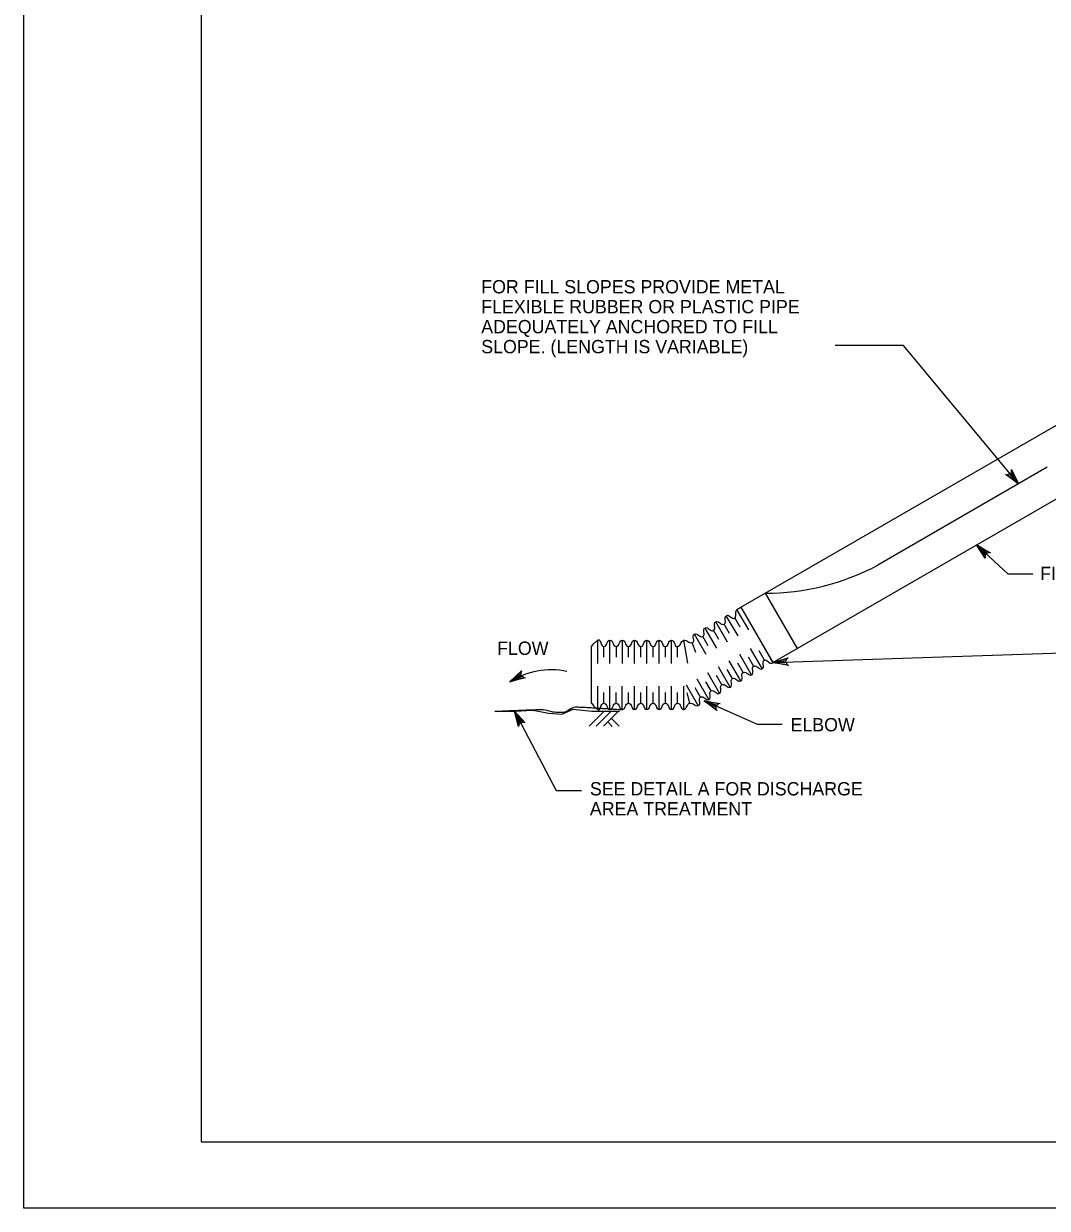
# Model space of a CAD drawing. Extents: x 636462 to 637367, y 299944 to 300538.
# Drawn here: x 636461.9 to 636692.5, y 299944.4 to 300211.3 of the extents above; entities that cross this region are included whole.
import ezdxf

# ---------------------------------------------------------------- set-up
doc = ezdxf.new("R2010")
doc.units = 0
for name, color, linetype in [('1', 7, 'Continuous'), ('Default', 7, 'Continuous'), ('PLT-BNDY', 7, 'Continuous')]:
    doc.layers.add(name, color=color, linetype=linetype)

# ---------------------------------------------------------------- blocks, each defined once
blk = doc.blocks.new('SC9446')
at = {"layer": 'Default'}
blk.add_line((0, 0), (0, 0), dxfattribs=at)

msp = doc.modelspace()

# ---------------------------------------------------------------- linework, layer by layer
at = {"layer": '1'}
msp.add_lwpolyline([(637287.91, 299959.45), (637287.91, 300523.45), (636501.91, 300523.45), (636501.91, 299959.45), (637287.91, 299959.45), (637287.91, 299985.81), (637087.91, 299985.81), (637087.91, 300050.49), (637287.91, 300050.49), (637287.91, 300079.45), (637087.91, 300079.45), (637087.91, 299959.45), (637166.72, 299959.45), (637166.72, 299985.81), (637166.72, 299959.45), (637243.72, 299959.45), (637243.72, 299985.81), (637243.72, 299973.49), (637287.91, 299973.49)], dxfattribs=at)
at = {"layer": 'Default'}
for p, q in [((636628.96, 300083.01), (636710.74, 300130.22)), ((636636.14, 300070.58), (636717.92, 300117.79)), ((636692.52, 300111.42), (636654.36, 300089.38)), ((636623.51, 300079.86), (636628.96, 300083.01)), ((636628.96, 300083.01), (636636.14, 300070.58)), ((636622.61, 300079.34), (636623.51, 300079.86)), ((636625.25, 300074.79), (636622.61, 300079.34)), ((636623.51, 300079.86), (636630.69, 300067.43)), ((636620.45, 300072.02), (636617.82, 300076.57)), ((636622.85, 300073.4), (636620.21, 300077.96)), ((636623.31, 300075.36), (636622.11, 300077.45)), ((636615.65, 300069.25), (636613.02, 300073.8)), ((636618.05, 300070.63), (636615.42, 300075.19)), ((636618.52, 300072.59), (636617.31, 300074.68)), ((636620.92, 300073.98), (636619.71, 300076.07)), ((636589.85, 300058.24), (636589.85, 300071.04)), ((636591.23, 300067.16), (636591.23, 300072.42)), ((636592.62, 300068.62), (636592.62, 300071.04)), ((636594, 300067.16), (636594, 300072.42)), ((636595.39, 300071.04), (636595.39, 300068.62)), ((636596.77, 300072.42), (636596.77, 300067.16)), ((636598.16, 300068.62), (636598.16, 300071.04)), ((636599.54, 300067.16), (636599.54, 300072.42)), ((636600.93, 300068.62), (636600.93, 300071.04)), ((636602.31, 300067.16), (636602.31, 300072.42)), ((636603.7, 300068.62), (636603.7, 300071.04)), ((636605.08, 300067.16), (636605.08, 300072.42)), ((636606.47, 300068.62), (636606.47, 300071.04)), ((636607.85, 300067.16), (636607.85, 300072.42)), ((636609.24, 300068.62), (636609.24, 300071.04)), ((636611.54, 300067.24), (636610.62, 300072.42)), ((636613.34, 300069.64), (636612.51, 300071.91)), ((636616.12, 300071.21), (636614.91, 300073.3)), ((636630.69, 300067.43), (636628.06, 300071.99)), ((636625.89, 300064.66), (636623.26, 300069.22)), ((636626.4, 300066.55), (636625.19, 300068.64)), ((636628.29, 300066.04), (636625.66, 300070.6)), ((636628.8, 300067.93), (636627.59, 300070.03)), ((636630.69, 300067.43), (636636.14, 300070.58)), ((636621.09, 300061.89), (636618.46, 300066.45)), ((636621.6, 300063.78), (636620.39, 300065.87)), ((636623.49, 300063.27), (636620.86, 300067.83)), ((636624, 300065.17), (636622.79, 300067.26)), ((636616.3, 300059.12), (636613.67, 300063.68)), ((636616.8, 300061.01), (636615.6, 300063.1)), ((636618.7, 300060.5), (636616.06, 300065.06)), ((636619.2, 300062.4), (636617.99, 300064.49)), ((636591.23, 300056.86), (636591.23, 300062.12)), ((636592.62, 300058.24), (636592.62, 300060.65)), ((636594, 300056.86), (636594, 300062.12)), ((636595.39, 300058.24), (636595.39, 300060.66)), ((636596.77, 300056.86), (636596.77, 300062.12)), ((636598.16, 300058.24), (636598.16, 300060.66)), ((636599.54, 300056.86), (636599.54, 300062.12)), ((636600.93, 300058.24), (636600.93, 300060.66)), ((636602.31, 300056.86), (636602.31, 300062.12)), ((636603.7, 300058.24), (636603.7, 300060.66)), ((636605.08, 300056.86), (636605.08, 300062.12)), ((636606.47, 300058.24), (636606.47, 300060.66)), ((636607.85, 300056.86), (636607.85, 300062.12)), ((636609.24, 300058.24), (636609.24, 300060.66)), ((636610.62, 300056.86), (636610.62, 300062.12)), ((636613.9, 300057.73), (636611.27, 300062.29)), ((636612.01, 300058.24), (636611.38, 300060.57)), ((636614.4, 300059.63), (636613.2, 300061.72)), ((636589.31, 300053.08), (636592.68, 300056.46)), ((636590.88, 300053.08), (636594.27, 300056.47)), ((636592.52, 300053.08), (636595.9, 300056.47)), ((636593.48, 300054.04), (636594.49, 300053.03)), ((636594.29, 300054.86), (636596.07, 300053.08))]:
    msp.add_line(p, q, dxfattribs=at)
for points in [[(636686.04, 300107.67), (636660.14, 300138.85), (636644.73, 300138.85)], [(636684.45, 300110.56), (636684.45, 300110.91), (636686.04, 300107.67), (636684.45, 300110.56), (636684.29, 300110.17), (636686.04, 300107.67), (636683.9, 300109.83), (636683.49, 300109.73), (636686.04, 300107.67), (636683.12, 300109.78), (636683.49, 300109.73)], [(636676.6, 300093.94), (636683.62, 300087.36), (636689.29, 300087.36)], [(636678.49, 300091.24), (636678.53, 300090.89), (636676.6, 300093.94), (636678.49, 300091.24), (636678.61, 300091.64), (636676.6, 300093.94), (636678.97, 300092.02), (636679.36, 300092.17), (636676.6, 300093.94), (636679.74, 300092.16), (636679.36, 300092.17)], [(636633.95, 300066.95), (636634.23, 300066.75), (636630.68, 300067.4), (636633.95, 300066.95), (636633.73, 300067.32), (636630.68, 300067.4), (636633.69, 300067.84), (636633.85, 300068.22), (636630.68, 300067.4), (636634.12, 300068.49), (636633.85, 300068.22)], [(636630.69, 300067.43), (636729.67, 300070.74), (636735.34, 300070.74)], [(636574.59, 300064.05), (636574.94, 300063.98), (636571.45, 300063.05), (636574.59, 300064.05), (636574.24, 300064.28), (636571.45, 300063.05), (636573.98, 300064.73), (636573.96, 300065.15), (636571.45, 300063.05), (636574.09, 300065.51), (636573.96, 300065.15)], [(636617.92, 300056.9), (636618.08, 300056.59), (636615.24, 300058.81), (636617.92, 300056.9), (636617.9, 300057.32), (636615.24, 300058.81), (636618.11, 300057.8), (636618.43, 300058.07), (636615.24, 300058.81), (636618.79, 300058.18), (636618.43, 300058.07)], [(636615.48, 300058.69), (636627.15, 300053.49), (636632.82, 300053.49)], [(636568.31, 300056.47), (636572.48, 300056.47), (636576.66, 300056.71), (636580.14, 300056.01), (636583.16, 300055.78), (636585.71, 300056.94), (636589.89, 300056.47), (636596.16, 300056.47)], [(636572.48, 300056.47), (636581.88, 300038.57), (636587.55, 300038.57)], [(636573.46, 300053.33), (636573.39, 300052.98), (636572.48, 300056.47), (636573.46, 300053.33), (636573.69, 300053.68), (636572.48, 300056.47), (636574.15, 300053.93), (636574.57, 300053.95), (636572.48, 300056.47), (636574.92, 300053.82), (636574.57, 300053.95)]]:
    msp.add_lwpolyline(points, dxfattribs=at)
for centre, radius, start, end in [((636629.06, 300136.39), 53.38, 269.892, 298.2877), ((636580.73, 300048.58), 17.19, 78.1581, 122.6576)]:
    msp.add_arc(centre, radius, start, end, dxfattribs=at)
for points in [[(636589.85, 300071.04), (636590.31, 300071.65), (636590.77, 300072.09), (636591.23, 300072.42), (636591.7, 300072.75), (636592.16, 300071.04), (636592.62, 300071.04), (636593.08, 300071.04), (636593.54, 300072.42), (636594, 300072.42), (636594.47, 300072.42), (636594.93, 300071.04), (636595.39, 300071.04), (636595.85, 300071.04), (636596.31, 300072.42), (636596.77, 300072.42), (636597.24, 300072.42), (636597.7, 300071.04), (636598.16, 300071.04), (636598.62, 300071.04), (636599.08, 300072.42), (636599.54, 300072.42), (636600, 300072.42), (636600.47, 300071.04), (636600.93, 300071.04), (636601.39, 300071.04), (636601.85, 300072.42), (636602.31, 300072.42), (636602.77, 300072.42), (636603.24, 300071.04), (636603.7, 300071.04), (636604.16, 300071.04), (636604.62, 300072.42), (636605.08, 300072.42), (636605.54, 300072.42), (636606, 300071.04), (636606.47, 300071.04), (636606.93, 300071.04), (636607.39, 300072.42), (636607.85, 300072.42), (636608.31, 300072.42), (636608.77, 300070.95), (636609.24, 300071.04), (636609.7, 300071.12), (636610.16, 300072.3), (636610.62, 300072.42), (636611.08, 300072.54), (636612.01, 300071.73), (636612.51, 300071.91), (636613.02, 300072.1), (636612.62, 300073.57), (636613.02, 300073.8), (636613.42, 300074.03), (636614.51, 300073.07), (636614.91, 300073.3), (636615.31, 300073.53), (636615.02, 300074.96), (636615.42, 300075.19), (636615.82, 300075.42), (636616.91, 300074.45), (636617.31, 300074.68), (636617.71, 300074.91), (636617.42, 300076.34), (636617.82, 300076.57), (636618.22, 300076.8), (636619.31, 300075.84), (636619.71, 300076.07), (636620.11, 300076.3), (636619.82, 300077.73), (636620.21, 300077.96), (636620.61, 300078.19), (636621.71, 300077.22), (636622.11, 300077.45), (636622.51, 300077.68), (636622.21, 300079.11), (636622.61, 300079.34)], [(636589.85, 300058.24), (636590.31, 300057.63), (636590.77, 300057.18), (636591.23, 300056.86), (636591.7, 300056.53), (636592.16, 300058.24), (636592.62, 300058.24), (636593.08, 300058.24), (636593.54, 300056.86), (636594, 300056.86), (636594.47, 300056.86), (636594.93, 300058.24), (636595.39, 300058.24), (636595.85, 300058.24), (636596.31, 300056.86), (636596.77, 300056.86), (636597.24, 300056.86), (636597.7, 300058.24), (636598.16, 300058.24), (636598.62, 300058.24), (636599.08, 300056.86), (636599.54, 300056.86), (636600, 300056.86), (636600.47, 300058.24), (636600.93, 300058.24), (636601.39, 300058.24), (636601.85, 300056.86), (636602.31, 300056.86), (636602.77, 300056.86), (636603.24, 300058.24), (636603.7, 300058.24), (636604.16, 300058.24), (636604.62, 300056.86), (636605.08, 300056.86), (636605.54, 300056.86), (636606, 300058.24), (636606.47, 300058.24), (636606.93, 300058.24), (636607.39, 300056.86), (636607.85, 300056.86), (636608.31, 300056.86), (636608.77, 300058.24), (636609.24, 300058.24), (636609.7, 300058.24), (636610.16, 300056.77), (636610.62, 300056.86), (636611.08, 300056.94), (636611.54, 300058.12), (636612.01, 300058.24), (636612.47, 300058.37), (636613.39, 300057.55), (636613.9, 300057.73), (636614.41, 300057.92), (636614, 300059.4), (636614.4, 300059.63), (636614.8, 300059.86), (636615.9, 300058.89), (636616.3, 300059.12), (636616.7, 300059.35), (636616.4, 300060.78), (636616.8, 300061.01), (636617.2, 300061.24), (636618.3, 300060.27), (636618.7, 300060.5), (636619.1, 300060.73), (636618.8, 300062.17), (636619.2, 300062.4), (636619.6, 300062.63), (636620.69, 300061.66), (636621.09, 300061.89), (636621.49, 300062.12), (636621.2, 300063.55), (636621.6, 300063.78), (636622, 300064.01), (636623.09, 300063.04), (636623.49, 300063.27), (636623.89, 300063.5), (636623.6, 300064.94), (636624, 300065.17), (636624.4, 300065.4), (636625.49, 300064.43), (636625.89, 300064.66), (636626.29, 300064.89), (636626, 300066.32), (636626.4, 300066.55), (636626.8, 300066.78), (636627.89, 300065.81), (636628.29, 300066.04), (636628.69, 300066.27), (636628.4, 300067.7), (636628.8, 300067.93), (636629.2, 300068.16), (636630.45, 300066.81), (636630.69, 300067.43)], [(636596.73, 300056.74), (636595.7, 300056.8), (636594.66, 300056.86), (636593.63, 300056.93), (636592.66, 300056.99), (636591.69, 300057.06), (636590.73, 300057.12), (636589.44, 300057.21), (636588.14, 300057.27), (636586.85, 300057.32), (636585.45, 300057.37), (636584.18, 300056.17), (636582.79, 300056.16), (636581.11, 300056.14), (636579.44, 300056.8), (636577.75, 300056.74), (636576.01, 300056.68), (636574.26, 300056.62), (636572.52, 300056.54), (636571.04, 300056.48), (636569.55, 300056.42), (636568.07, 300056.35)]]:
    msp.add_open_spline(points, degree=3, dxfattribs=at)
at = {"layer": 'PLT-BNDY'}
msp.add_lwpolyline([(636461.91, 300538.45), (637302.91, 300538.45), (637302.91, 299944.45), (636461.91, 299944.45)], close=True, dxfattribs=at)

# ---------------------------------------------------------------- block references
at = {"layer": 'Default', "xscale": 2.753831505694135, "yscale": 2.753831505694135}
msp.add_blockref('SC9446', (636596.77, 300062.12), dxfattribs=at)

# ---------------------------------------------------------------- texts
at = {"layer": 'Default'}
for s, p in [('FOR FILL SLOPES PROVIDE METAL', (636564.99, 300150.58)), ('FLEXIBLE RUBBER OR PLASTIC PIPE', (636564.99, 300146.09)), ('ADEQUATELY ANCHORED TO FILL', (636564.99, 300141.59)), ('SLOPE. (LENGTH IS VARIABLE)', (636564.99, 300137.09)), ('FILL SLOPE', (636690.9, 300085.98)), ('FLOW', (636568.57, 300069.14)), ('ELBOW', (636634.67, 300051.91)), ('SEE DETAIL A FOR DISCHARGE', (636589.47, 300037.47)), ('AREA TREATMENT', (636589.47, 300032.98))]:
    msp.add_text(s, height=2.998, dxfattribs=at).set_placement(p)

doc.saveas('drawing.dxf')
